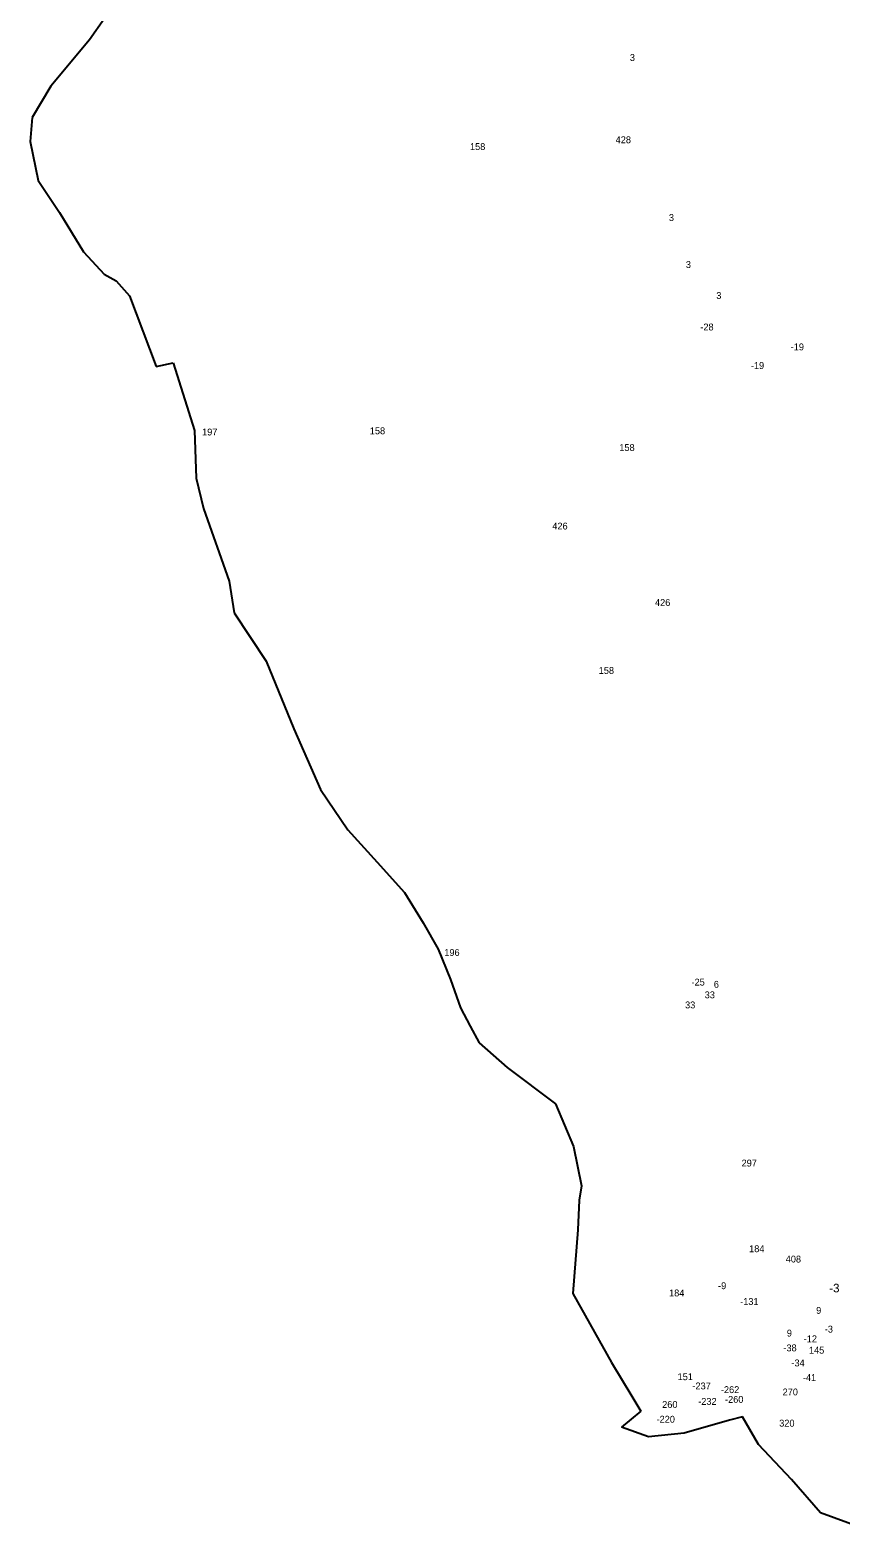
# Model space of a CAD drawing. Extents: x -784109 to -782312, y -974244 to -970866.
# Drawn here: x -784092 to -783412, y -973813 to -972551 of the extents above; entities that cross this region are included whole.
import ezdxf

# ---------------------------------------------------------------- set-up
doc = ezdxf.new("R2010")
doc.units = 0
doc.layers.add('Vrstva 13', color=7, linetype='Continuous')
doc.layers.add('Vrstva 24', color=7, linetype='Continuous')

msp = doc.modelspace()

# ---------------------------------------------------------------- linework, layer by layer
at = {"layer": 'Vrstva 13'}
for p, q in [((-784016.84, -972522.67), (-784042.05, -972558.63)), ((-784042.05, -972558.63), (-784074.49, -972597.62)), ((-784074.49, -972597.62), (-784090.13, -972623.78)), ((-784090.13, -972623.78), (-784091.76, -972643.86)), ((-784091.76, -972643.86), (-784085.02, -972676.55)), ((-784085.02, -972676.55), (-784067.06, -972703.46)), ((-784067.06, -972703.46), (-784046.99, -972736.21)), ((-784046.99, -972736.21), (-784029.66, -972755)), ((-784029.66, -972755), (-784019.74, -972760.61)), ((-784019.74, -972760.61), (-784008.36, -972773.04)), ((-784008.36, -972773.04), (-783986.05, -972832.29)), ((-783986.05, -972832.29), (-783971.79, -972829.4)), ((-783971.79, -972829.4), (-783954, -972886.04)), ((-783954, -972886.04), (-783952.51, -972925.85)), ((-783952.51, -972925.85), (-783946.52, -972951.3)), ((-783946.52, -972951.3), (-783924.93, -973012.24)), ((-783924.93, -973012.24), (-783920.71, -973038.63)), ((-783920.71, -973038.63), (-783893.84, -973079.02)), ((-783893.84, -973079.02), (-783870.85, -973135.76)), ((-783870.85, -973135.76), (-783848.32, -973186.66)), ((-783848.32, -973186.66), (-783825.54, -973220.41)), ((-783825.54, -973220.41), (-783801, -973247.62)), ((-783801, -973247.62), (-783778.12, -973272.83)), ((-783778.12, -973272.83), (-783762.43, -973298.37)), ((-783762.43, -973298.37), (-783749.84, -973320.42)), ((-783749.84, -973320.42), (-783739.47, -973345.76)), ((-783739.47, -973345.76), (-783730.94, -973369.39)), ((-783730.94, -973369.39), (-783723.07, -973384.75)), ((-783723.07, -973384.75), (-783715.46, -973398.93)), ((-783715.46, -973398.93), (-783691.97, -973419.41)), ((-783691.97, -973419.41), (-783651.57, -973449.86)), ((-783651.57, -973449.86), (-783636.48, -973485.51)), ((-783636.48, -973485.51), (-783629.52, -973518.47)), ((-783629.52, -973518.47), (-783631.69, -973530.54)), ((-783631.69, -973530.54), (-783632.61, -973555.55)), ((-783632.61, -973555.55), (-783636.83, -973608.72)), ((-783636.83, -973608.72), (-783604.55, -973666.62)), ((-783604.55, -973666.62), (-783587.49, -973694.71)), ((-783587.49, -973694.71), (-783580, -973707.19)), ((-783580, -973707.19), (-783596, -973720.71)), ((-783573.4, -973728.68), (-783596, -973720.71)), ((-783505.68, -973714.94), (-783543.68, -973725.66)), ((-783494.75, -973711.95), (-783505.68, -973714.94)), ((-783481.32, -973735.17), (-783494.75, -973711.95)), ((-783543.68, -973725.66), (-783573.4, -973728.68)), ((-783453.64, -973764.44), (-783481.32, -973735.17)), ((-783429.39, -973792.54), (-783453.64, -973764.44)), ((-783371.73, -973813.41), (-783429.39, -973792.54))]:
    msp.add_line(p, q, dxfattribs=at)

# ---------------------------------------------------------------- texts
at = {"layer": 'Vrstva 24'}
for s, height, p in [('3', 5.76, (-783589.123, -972576.432)), ('158', 5.76, (-783723.105, -972651.052)), ('428', 5.76, (-783601.028, -972645.332)), ('3', 5.76, (-783556.393, -972710.502)), ('3', 5.76, (-783542.183, -972749.832)), ('3', 5.76, (-783516.663, -972775.782)), ('-28', 5.76, (-783530.056, -972802.156)), ('-19', 5.76, (-783454.322, -972818.819)), ('-19', 5.76, (-783487.69, -972834.399)), ('197', 5.76, (-783947.631, -972890.102)), ('158', 5.76, (-783807.085, -972889.112)), ('158', 5.76, (-783597.945, -972903.112)), ('426', 5.76, (-783654.112, -972968.862)), ('426', 5.76, (-783568.062, -973032.922)), ('158', 5.76, (-783615.225, -973089.802)), ('196', 5.76, (-783744.643, -973326.062)), ('-25', 5.76, (-783537.456, -973350.858)), ('33', 5.76, (-783526.393, -973361.512)), ('6', 5.76, (-783518.746, -973352.662)), ('33', 5.76, (-783542.843, -973369.952)), ('297', 5.76, (-783495.488, -973502.382)), ('184', 5.76, (-783489.171, -973574.142)), ('408', 5.76, (-783458.485, -973582.792)), ('184', 5.76, (-783556.251, -973611.192)), ('-9', 5.76, (-783515.183, -973605.114)), ('-3', 7.2, (-783421.978, -973607.797)), ('-131', 5.76, (-783496.687, -973618.374)), ('9', 5.76, (-783432.956, -973625.772)), ('9', 5.76, (-783457.546, -973644.812)), ('-12', 5.76, (-783443.389, -973649.591)), ('-3', 5.76, (-783425.752, -973641.455)), ('-38', 5.76, (-783460.432, -973657.212)), ('145', 5.76, (-783439.011, -973659.112)), ('-34', 5.76, (-783453.738, -973669.801)), ('151', 5.76, (-783549.088, -973681.342)), ('-237', 5.76, (-783536.672, -973689.071)), ('-41', 5.76, (-783444.11, -973682.059)), ('-232', 5.76, (-783531.823, -973702.009)), ('-262', 5.76, (-783512.816, -973692.169)), ('-260', 5.76, (-783509.373, -973700.349)), ('270', 5.76, (-783461.101, -973694.102)), ('260', 5.76, (-783562.043, -973704.582)), ('-220', 5.76, (-783566.744, -973716.961)), ('320', 5.76, (-783463.939, -973720.242))]:
    msp.add_text(s, height=height, dxfattribs=at).set_placement(p)

doc.saveas('drawing.dxf')
